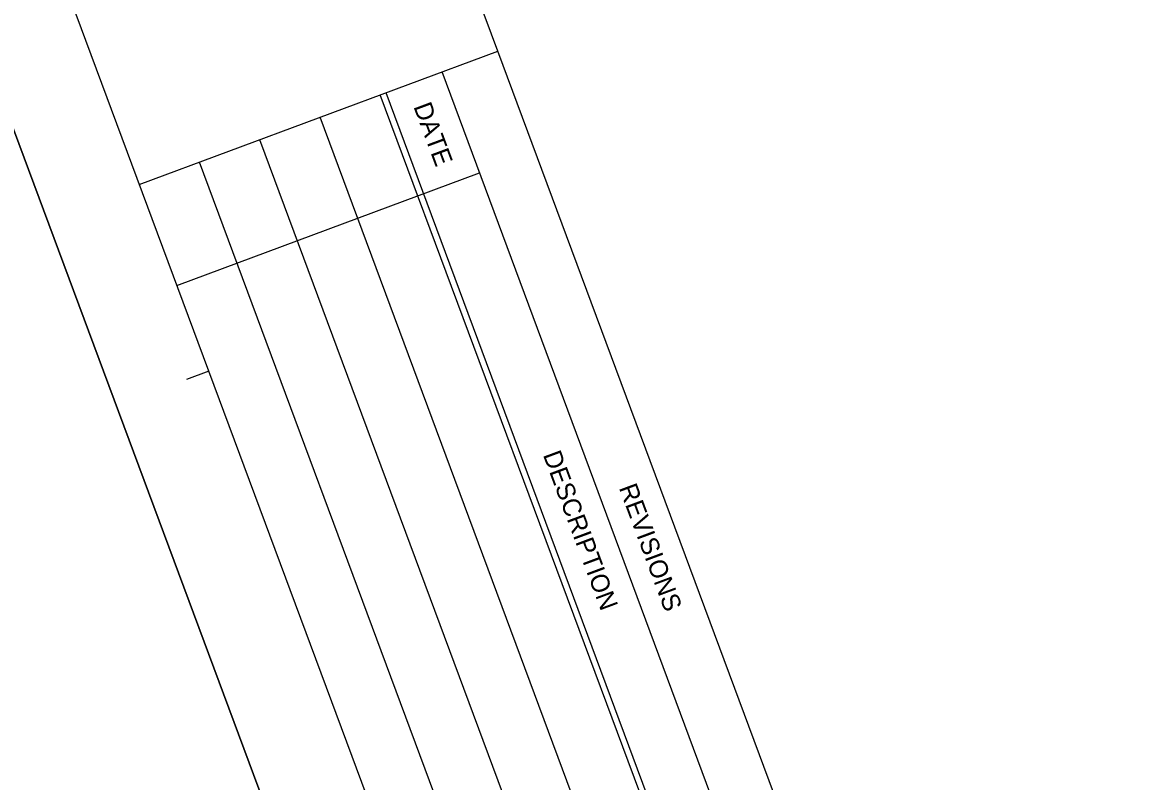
# Model space of a CAD drawing. Extents: x 1040172 to 1040822, y 1127790 to 1128580.
# Drawn here: x 1040280.8 to 1040398.7, y 1128069 to 1128148.3 of the extents above; entities that cross this region are included whole.
import ezdxf

# ---------------------------------------------------------------- set-up
doc = ezdxf.new("R2010")
doc.units = 0
for name, color, linetype in [('clip boundary', 7, 'Continuous'), ('SHEET_BORDER', 7, 'Continuous'), ('SHEET_BORDER_CUT', 7, 'Continuous'), ('SHEET_BORDER_STAMPBOX', 7, 'Continuous')]:
    doc.layers.add(name, color=color, linetype=linetype)

msp = doc.modelspace()

# ---------------------------------------------------------------- linework, layer by layer
at = {"layer": 'clip boundary'}
msp.add_lwpolyline([(1040584.48, 1128580.33), (1040821.52, 1127942.99), (1040409.12, 1127789.61), (1040172.08, 1128426.95)], close=True, dxfattribs=at)
at = {"layer": 'SHEET_BORDER'}
for p, q in [((1040293.01, 1128131.38), (1040330.5, 1128145.33)), ((1040293.01, 1128131.38), (1040330.5, 1128145.33)), ((1040447.57, 1127830.58), (1040330.5, 1128145.33)), ((1040366.44, 1128030.8), (1040324.66, 1128143.15)), ((1040366.44, 1128030.8), (1040324.66, 1128143.15)), ((1040359.99, 1128028.4), (1040318.21, 1128140.75)), ((1040360.59, 1128028.62), (1040318.81, 1128140.98)), ((1040360.59, 1128028.62), (1040318.81, 1128140.98)), ((1040353.7, 1128026.05), (1040311.91, 1128138.41)), ((1040347.4, 1128023.71), (1040305.61, 1128136.07)), ((1040341.1, 1128021.37), (1040299.31, 1128133.73)), ((1040300.27, 1128111.88), (1040297.93, 1128111))]:
    msp.add_line(p, q, dxfattribs=at)
msp.add_lwpolyline([(1040412.42, 1127817.51), (1040409.2, 1127818.98), (1040191.33, 1128404.77), (1040192.81, 1128407.99), (1040581.19, 1128552.44), (1040584.4, 1128550.96), (1040802.27, 1127965.17), (1040800.8, 1127961.95)], close=True, dxfattribs=at)
msp.add_lwpolyline([(1040296.94, 1128120.84), (1040328.58, 1128132.61)], dxfattribs=at)
at = {"layer": 'SHEET_BORDER_CUT'}
msp.add_lwpolyline([(1040172.08, 1128426.95), (1040409.12, 1127789.61), (1040821.52, 1127942.99), (1040584.48, 1128580.33)], close=True, dxfattribs=at)
at = {"layer": 'SHEET_BORDER_STAMPBOX'}
msp.add_line((1040330.5, 1128145.33), (1040283.07, 1128272.85), dxfattribs=at)

# ---------------------------------------------------------------- texts
at = {"layer": 'SHEET_BORDER'}
for s, p in [('DATE', (1040321.65, 1128139.54)), ('DESCRIPTION', (1040335.19, 1128103.13)), ('REVISIONS', (1040343.13, 1128099.68))]:
    msp.add_text(s, height=1.92, rotation=290.4011, dxfattribs=at).set_placement(p)

doc.saveas('drawing.dxf')
